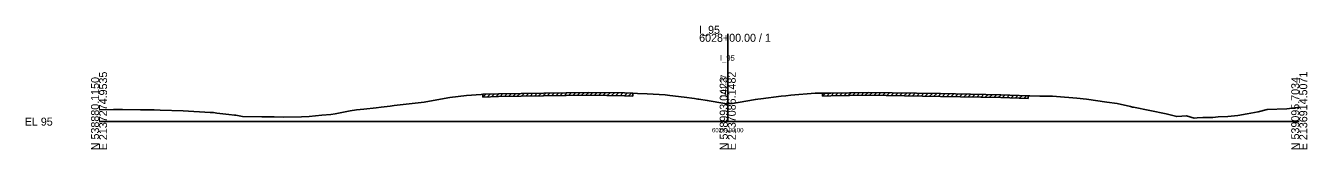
# Model space of a CAD drawing. Extents: x -12534 to 3403, y -1332 to 21983.
# Drawn here: x 974.3 to 1422.8, y 15490.3 to 15533.6 of the extents above; entities that cross this region are included whole.
import ezdxf

# ---------------------------------------------------------------- set-up
doc = ezdxf.new("R2010")
doc.units = 0
for name, color, linetype in [('RD_GPK_XS_Cell', 7, 'Continuous'), ('RD_XS_ExGround', 7, 'Continuous'), ('RD_XS_ExPaveRet', 7, 'Continuous'), ('RD_XS_TX_Baseline', 7, 'Continuous'), ('RD_XS_TX_Elev_EX', 7, 'Continuous'), ('RD_XS_TX_Station', 7, 'Continuous')]:
    doc.layers.add(name, color=color, linetype=linetype)

msp = doc.modelspace()

# ---------------------------------------------------------------- linework, layer by layer
at = {"layer": 'RD_GPK_XS_Cell'}
for p, q in [((1220, 15500), (1220, 15530.72)), ((1000, 15500), (1220, 15500)), ((1220, 15500), (1420, 15500))]:
    msp.add_line(p, q, dxfattribs=at)
at = {"layer": 'RD_XS_ExGround'}
msp.add_lwpolyline([(1000, 15504.18), (1005.08, 15504.2), (1008.24, 15504.22), (1014.48, 15504.18), (1019.24, 15504.1), (1021.44, 15504.03), (1029.44, 15503.82), (1038.83, 15503.22), (1040.01, 15503.18), (1041.2, 15502.98), (1045.37, 15502.49), (1047.4, 15502.27), (1047.81, 15502.21), (1050.25, 15501.77), (1057.01, 15501.72), (1061.24, 15501.69), (1064.67, 15501.59), (1070.82, 15501.65), (1073.52, 15501.83), (1077.91, 15502.23), (1081.13, 15502.54), (1082.61, 15502.74), (1087.93, 15503.82), (1090.07, 15504.13), (1092.67, 15504.33), (1096.95, 15504.85), (1098.74, 15505.03), (1101.89, 15505.45), (1103.26, 15505.64), (1109.62, 15506.36), (1113.77, 15506.84), (1122.04, 15508.34), (1122.81, 15508.48), (1128.63, 15509.17), (1133.68, 15509.54), (1134.33, 15509.56), (1139.75, 15509.76), (1171.4, 15510.24), (1183.85, 15510.04), (1186.79, 15509.94), (1188.43, 15509.8), (1191.78, 15509.69), (1198.14, 15509.37), (1199.79, 15509.17), (1204.76, 15508.53), (1208.4, 15508.06), (1209.49, 15507.86), (1209.88, 15507.8), (1212.82, 15507.44), (1218.94, 15506.34), (1219.49, 15506.25), (1220, 15506.27), (1221.64, 15506.34), (1223.61, 15506.67), (1229.68, 15507.76), (1230.58, 15507.89), (1231.59, 15507.98), (1238.73, 15508.87), (1240.28, 15509.07), (1242.09, 15509.2), (1250.65, 15509.97), (1253.14, 15509.92), (1256.1, 15510), (1269.15, 15510.22), (1294.4, 15509.83), (1315.59, 15509.43), (1325.17, 15509.06), (1325.68, 15509.04), (1329.21, 15508.94), (1333.66, 15508.85), (1335.09, 15508.81), (1342.16, 15508.25), (1345.59, 15507.88), (1352.7, 15506.84), (1356.29, 15506.32), (1360.98, 15505.25), (1361.69, 15505.08), (1362.01, 15505.02), (1373.47, 15502.72), (1377.11, 15501.78), (1378.94, 15501.86), (1380.53, 15501.99), (1383.26, 15501.26), (1384.32, 15501.29), (1386.27, 15501.47), (1389.22, 15501.4), (1389.76, 15501.44), (1391.61, 15501.63), (1395.03, 15501.81), (1398.48, 15502.12), (1401.76, 15502.7), (1405.57, 15503.46), (1408.83, 15504.19), (1415.71, 15504.52), (1419.35, 15504.9), (1420, 15504.9)], dxfattribs=at)
at = {"layer": 'RD_XS_ExPaveRet'}
for p, q in [((1134.33, 15508.56), (1135.37, 15509.6)), ((1134.33, 15508.56), (1134.33, 15509.56)), ((1134.33, 15508.56), (1139.75, 15508.76)), ((1135.83, 15508.61), (1136.87, 15509.65)), ((1137.33, 15508.67), (1138.37, 15509.71)), ((1138.83, 15508.73), (1139.87, 15509.76)), ((1139.75, 15508.76), (1171.4, 15509.24)), ((1140.33, 15508.77), (1141.35, 15509.79)), ((1141.83, 15508.79), (1142.85, 15509.81)), ((1143.33, 15508.82), (1144.35, 15509.83)), ((1144.83, 15508.84), (1145.85, 15509.85)), ((1146.33, 15508.86), (1147.35, 15509.88)), ((1147.83, 15508.88), (1148.85, 15509.9)), ((1149.33, 15508.91), (1150.35, 15509.92)), ((1150.83, 15508.93), (1151.85, 15509.94)), ((1152.33, 15508.95), (1153.35, 15509.97)), ((1153.83, 15508.97), (1154.85, 15509.99)), ((1155.33, 15509), (1156.35, 15510.01)), ((1156.83, 15509.02), (1157.85, 15510.04)), ((1158.33, 15509.04), (1159.35, 15510.06)), ((1159.83, 15509.07), (1160.85, 15510.08)), ((1161.33, 15509.09), (1162.35, 15510.1)), ((1162.83, 15509.11), (1163.85, 15510.13)), ((1164.33, 15509.13), (1165.35, 15510.15)), ((1165.83, 15509.16), (1166.85, 15510.17)), ((1167.33, 15509.18), (1168.35, 15510.19)), ((1168.83, 15509.2), (1169.85, 15510.22)), ((1170.33, 15509.22), (1171.35, 15510.24)), ((1171.4, 15509.24), (1183.85, 15509.04)), ((1171.83, 15509.23), (1172.82, 15510.22)), ((1173.33, 15509.21), (1174.32, 15510.19)), ((1174.83, 15509.19), (1175.82, 15510.17)), ((1176.33, 15509.16), (1177.32, 15510.15)), ((1177.83, 15509.14), (1178.82, 15510.12)), ((1179.33, 15509.11), (1180.32, 15510.1)), ((1180.83, 15509.09), (1181.82, 15510.07)), ((1182.33, 15509.07), (1183.32, 15510.05)), ((1183.83, 15509.04), (1184.8, 15510.01)), ((1183.85, 15509.04), (1186.79, 15508.94)), ((1185.33, 15508.99), (1186.3, 15509.96)), ((1186.79, 15509.94), (1186.79, 15508.94)), ((1253.14, 15508.92), (1254.17, 15509.95)), ((1253.14, 15508.92), (1253.14, 15509.92)), ((1253.14, 15508.92), (1256.1, 15509)), ((1254.64, 15508.96), (1255.67, 15509.99)), ((1256.1, 15509), (1269.15, 15509.22)), ((1256.14, 15509), (1257.16, 15510.02)), ((1257.64, 15509.03), (1258.66, 15510.04)), ((1259.14, 15509.05), (1260.16, 15510.07)), ((1260.64, 15509.08), (1261.66, 15510.09)), ((1262.14, 15509.1), (1263.16, 15510.12)), ((1263.64, 15509.13), (1264.66, 15510.14)), ((1265.14, 15509.15), (1266.16, 15510.17)), ((1266.64, 15509.17), (1267.66, 15510.19)), ((1268.14, 15509.2), (1269.16, 15510.22)), ((1269.15, 15509.22), (1294.4, 15508.83)), ((1269.64, 15509.21), (1270.63, 15510.19)), ((1271.14, 15509.19), (1272.13, 15510.17)), ((1272.64, 15509.16), (1273.63, 15510.15)), ((1274.14, 15509.14), (1275.13, 15510.12)), ((1275.64, 15509.12), (1276.63, 15510.1)), ((1277.14, 15509.09), (1278.13, 15510.08)), ((1278.64, 15509.07), (1279.63, 15510.06)), ((1280.14, 15509.05), (1281.13, 15510.03)), ((1281.64, 15509.03), (1282.63, 15510.01)), ((1283.14, 15509), (1284.13, 15509.99)), ((1284.64, 15508.98), (1285.63, 15509.96)), ((1286.14, 15508.96), (1287.13, 15509.94)), ((1287.64, 15508.93), (1288.63, 15509.92)), ((1289.14, 15508.91), (1290.13, 15509.9)), ((1290.64, 15508.89), (1291.63, 15509.87)), ((1292.14, 15508.87), (1293.13, 15509.85)), ((1293.64, 15508.84), (1294.63, 15509.83)), ((1294.4, 15508.83), (1315.59, 15508.43)), ((1295.14, 15508.82), (1296.13, 15509.8)), ((1296.64, 15508.79), (1297.63, 15509.77)), ((1298.14, 15508.76), (1299.13, 15509.74)), ((1299.64, 15508.73), (1300.63, 15509.71)), ((1301.14, 15508.7), (1302.13, 15509.69)), ((1302.64, 15508.68), (1303.63, 15509.66)), ((1304.14, 15508.65), (1305.13, 15509.63)), ((1305.64, 15508.62), (1306.63, 15509.6)), ((1307.14, 15508.59), (1308.13, 15509.57)), ((1308.64, 15508.56), (1309.63, 15509.55)), ((1310.14, 15508.54), (1311.13, 15509.52)), ((1311.64, 15508.51), (1312.63, 15509.49)), ((1313.14, 15508.48), (1314.13, 15509.46)), ((1314.64, 15508.45), (1315.63, 15509.43)), ((1315.59, 15508.43), (1325.17, 15508.06)), ((1316.14, 15508.41), (1317.11, 15509.37)), ((1317.64, 15508.35), (1318.61, 15509.32)), ((1319.14, 15508.3), (1320.11, 15509.26)), ((1320.64, 15508.24), (1321.61, 15509.2)), ((1322.14, 15508.18), (1323.11, 15509.14)), ((1323.64, 15508.12), (1324.61, 15509.08)), ((1325.17, 15509.06), (1325.17, 15508.06))]:
    msp.add_line(p, q, dxfattribs=at)

# ---------------------------------------------------------------- texts
at = {"layer": 'RD_GPK_XS_Cell'}
for s, p in [('I_95', (1210, 15530.72)), ('6028+00.00 / 1', (1210, 15527.92)), ('EL 95', (974, 15498.6))]:
    msp.add_text(s, height=2.8, dxfattribs=at).set_placement(p)
for s, p in [('N 538880.1150', (1000, 15490)), ('E 2137274.9535', (1002.8, 15490)), ('N 538993.0423', (1220, 15490)), ('E 2137086.1482', (1222.8, 15490)), ('N 539095.7034', (1420, 15490)), ('E 2136914.5071', (1422.8, 15490))]:
    msp.add_text(s, height=2.8, rotation=90, dxfattribs=at).set_placement(p)
at = {"layer": 'RD_XS_TX_Baseline'}
msp.add_text('I_95', height=2, dxfattribs=at).set_placement((1217.28, 15521.27))
at = {"layer": 'RD_XS_TX_Elev_EX'}
msp.add_text('101.27', height=2, rotation=90, dxfattribs=at).set_placement((1219.5, 15508.27))
at = {"layer": 'RD_XS_TX_Station'}
msp.add_text('6028+00.00', height=1.5, dxfattribs=at).set_placement((1214.51, 15496.27))

doc.saveas('drawing.dxf')
